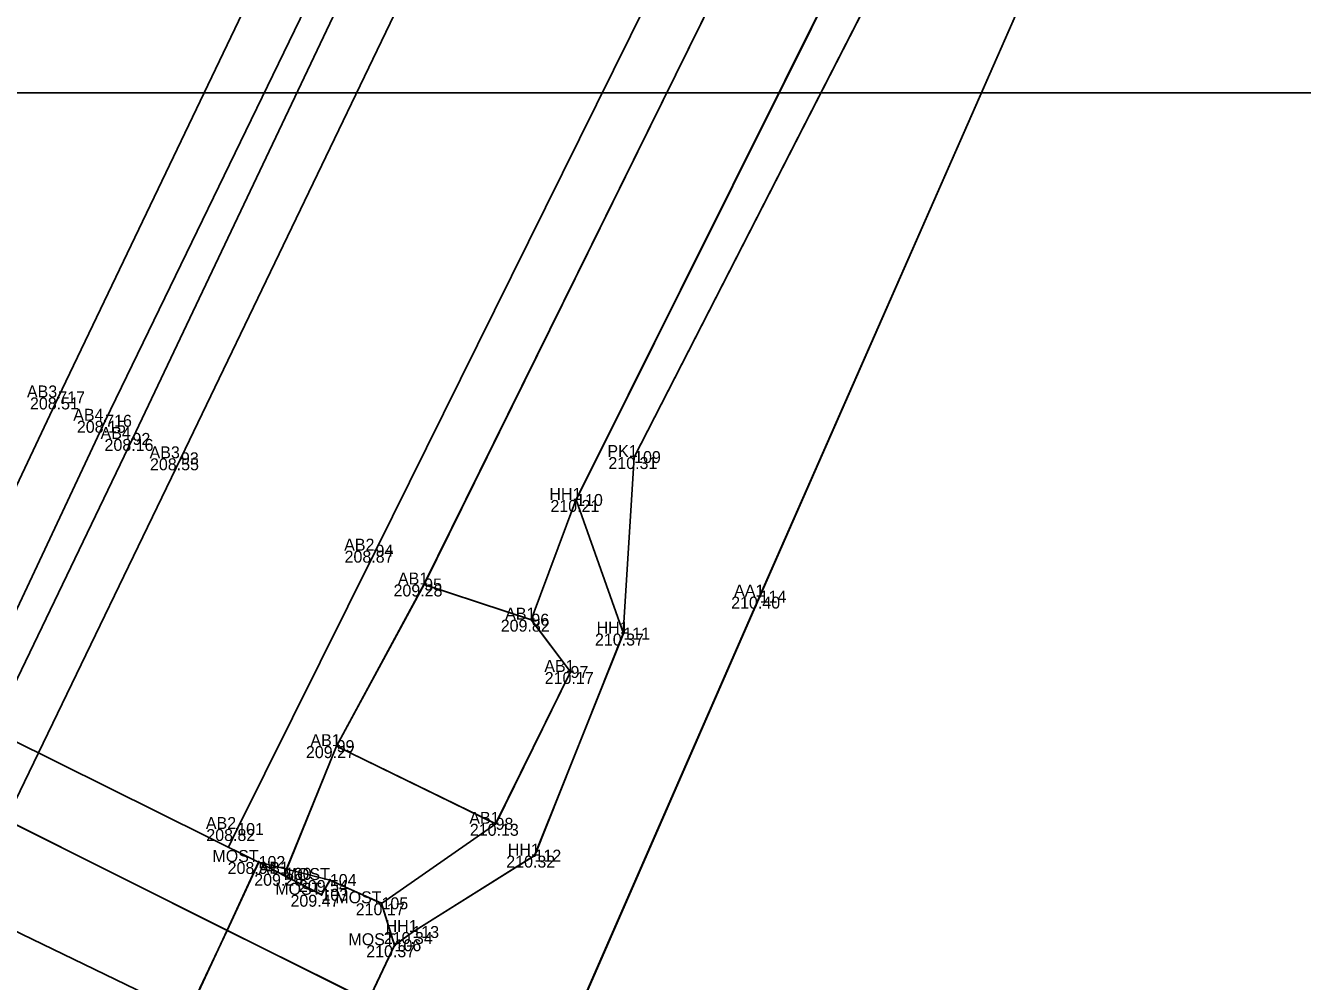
# Model space of a CAD drawing. Extents: x -263091 to -262565, y -1238731 to -1237092.
# Drawn here: x -262786.65 to -262765.31, y -1237679.73 to -1237663.76 of the extents above; entities that cross this region are included whole.
import ezdxf

# ---------------------------------------------------------------- set-up
doc = ezdxf.new("R2010")
doc.units = 0
for name, color, linetype in [('01_Hrana_betónu', 7, 'Continuous'), ('02_Oplotenie', 7, 'Continuous'), ('03_Asfalt', 7, 'Continuous'), ('04_Most', 7, 'Continuous'), ('05_Hrana_terénu', 7, 'Continuous'), ('07_Iné', 7, 'Continuous'), ('10', 7, 'Continuous'), ('Groma (21)', 7, 'Continuous'), ('Groma (22)', 7, 'Continuous'), ('Groma (23)', 7, 'Continuous'), ('Groma (24)', 7, 'Continuous'), ('U004_Betónové_panely', 7, 'Continuous'), ('U004_Ostatné_plochy', 7, 'Continuous'), ('U005_Betónové_panely', 7, 'Continuous'), ('U005_Betóny_prídavné', 7, 'Continuous'), ('U005_Ostatné_plochy', 7, 'Continuous'), ('U005_Zeleň_mimo', 7, 'Continuous'), ('U005_Zeleň_vnútro', 7, 'Continuous'), ('U005_Zeleň_zatrávňovač', 7, 'Continuous'), ('Vrstva 51', 7, 'Continuous')]:
    doc.layers.add(name, color=color, linetype=linetype)

msp = doc.modelspace()

# ---------------------------------------------------------------- linework, layer by layer
at = {"layer": '01_Hrana_betónu'}
for p, q in [((-262783.282, -1237678.876), (-262782.754, -1237677.736)), ((-262783.935, -1237680.285), (-262783.282, -1237678.876))]:
    msp.add_line(p, q, dxfattribs=at)
for points in [[(-262786.432, -1237675.911), (-262784.052, -1237670.991), (-262777.997, -1237658.39), (-262770.22, -1237641.884), (-262760.517, -1237621.621), (-262751.199, -1237602.266), (-262746.917, -1237592.345), (-262743.67, -1237583.59), (-262741.234, -1237574.416), (-262739.924, -1237566.213), (-262738.929, -1237556.596), (-262738.741, -1237547.665), (-262738.506, -1237524.618), (-262738.316, -1237501.393), (-262738.103, -1237478.98), (-262737.841, -1237459.175), (-262737.82, -1237425.07), (-262737.772, -1237401.714), (-262737.893, -1237377.738), (-262738.012, -1237356.488), (-262737.973, -1237332.295), (-262738.006, -1237318.022), (-262737.947, -1237310.645)], [(-262738.855, -1237311.192), (-262738.946, -1237318.051), (-262738.849, -1237332.413), (-262738.867, -1237356.312), (-262738.748, -1237377.69), (-262738.758, -1237401.69), (-262738.753, -1237425.185), (-262738.668, -1237459.096), (-262739.01, -1237478.875), (-262739.257, -1237501.361), (-262739.436, -1237524.506), (-262739.635, -1237547.624), (-262739.863, -1237556.5), (-262740.784, -1237566.075), (-262742.123, -1237574.161), (-262744.555, -1237583.315), (-262747.793, -1237592.067), (-262752.033, -1237601.877), (-262761.381, -1237621.164), (-262771.059, -1237641.465), (-262778.806, -1237657.918), (-262784.861, -1237670.667), (-262787.201, -1237675.529)], [(-262739.343, -1237311.485), (-262739.423, -1237318.909), (-262739.337, -1237332.42), (-262739.334, -1237355.849), (-262739.135, -1237377.701), (-262739.178, -1237401.786), (-262739.257, -1237424.031), (-262739.458, -1237458.924), (-262739.421, -1237479.296), (-262739.718, -1237500.116), (-262739.917, -1237524.824), (-262740.163, -1237546.913), (-262740.342, -1237556.649), (-262741.144, -1237564.78), (-262742.646, -1237573.838), (-262744.715, -1237582.455), (-262748.007, -1237591.229), (-262752.529, -1237601.669), (-262761.584, -1237620.386), (-262771.44, -1237641.076), (-262779.114, -1237657.574), (-262785.318, -1237670.364), (-262787.643, -1237675.31)], [(-262788.441, -1237674.914), (-262786.102, -1237669.974), (-262779.96, -1237657.146), (-262772.255, -1237640.671), (-262762.405, -1237620.082), (-262753.353, -1237601.237), (-262748.855, -1237590.92), (-262745.54, -1237582.117), (-262743.431, -1237573.688), (-262742.016, -1237564.7), (-262741.168, -1237556.501), (-262740.979, -1237546.892), (-262740.851, -1237524.752), (-262740.671, -1237500.08), (-262740.394, -1237479.483), (-262740.216, -1237458.955), (-262740.117, -1237423.647), (-262740.094, -1237401.75), (-262740.13, -1237377.708), (-262740.243, -1237355.929), (-262740.317, -1237332.345), (-262740.44, -1237318.894), (-262740.323, -1237312.076)], [(-262783.258, -1237677.486), (-262783.111, -1237677.185), (-262780.8, -1237672.534), (-262774.552, -1237659.911), (-262766.786, -1237643.656), (-262757.035, -1237623.248), (-262747.974, -1237603.808), (-262743.592, -1237593.531), (-262740.333, -1237584.524), (-262737.7, -1237574.963), (-262736.283, -1237566.732), (-262735.575, -1237556.629), (-262735.369, -1237547.722), (-262734.981, -1237524.159), (-262734.838, -1237501.704)], [(-262782.326, -1237677.959), (-262781.45, -1237675.8), (-262779.987, -1237673.099), (-262773.679, -1237660.319), (-262765.958, -1237644.106), (-262756.238, -1237623.625), (-262747.207, -1237604.197), (-262742.811, -1237593.79), (-262739.484, -1237584.835), (-262736.846, -1237575.127), (-262735.426, -1237566.88), (-262734.686, -1237556.753), (-262734.467, -1237547.755), (-262734.294, -1237524.216), (-262733.894, -1237501.859)], [(-262786.974, -1237677.031), (-262786.432, -1237675.911)]]:
    msp.add_lwpolyline(points, dxfattribs=at)
at = {"layer": '02_Oplotenie'}
msp.add_lwpolyline([(-262728.456, -1237307.793), (-262728.519, -1237318.579), (-262728.768, -1237332.338), (-262729.377, -1237356.238), (-262730.032, -1237378.843), (-262730.564, -1237401.661), (-262730.923, -1237425.563), (-262730.973, -1237458.163), (-262731.252, -1237478.578), (-262731.235, -1237502.529), (-262731.31, -1237524.311), (-262731.953, -1237547.895), (-262732.188, -1237556.779), (-262732.808, -1237567.174), (-262734.162, -1237576.139), (-262736.979, -1237586.017), (-262740.293, -1237594.798), (-262745.086, -1237605.537), (-262753.698, -1237624.773), (-262762.903, -1237643.627), (-262772.016, -1237662.266), (-262776.478, -1237670.97)], dxfattribs=at)
at = {"layer": '03_Asfalt'}
msp.add_lwpolyline([(-262724.746, -1237307.401), (-262727.828, -1237308.991), (-262728.093, -1237318.612), (-262728.491, -1237332.383), (-262729.117, -1237356.253), (-262729.803, -1237378.892), (-262730.272, -1237401.612), (-262730.633, -1237425.617), (-262730.625, -1237458.196), (-262731.018, -1237478.61), (-262730.917, -1237502.542), (-262731.001, -1237524.284), (-262731.468, -1237547.904), (-262731.892, -1237556.788), (-262732.535, -1237567.203), (-262733.679, -1237576.214), (-262736.504, -1237586.306), (-262740.104, -1237594.868), (-262744.783, -1237605.686), (-262753.189, -1237625.134), (-262761.527, -1237644.232), (-262769.984, -1237663.306), (-262774.379, -1237673.302), (-262777.928, -1237681.411)], dxfattribs=at)
at = {"layer": '04_Most'}
for points in [[(-262794.832, -1237673.105), (-262794.423, -1237672.239), (-262794.016, -1237671.765), (-262792.919, -1237672.236), (-262791.945, -1237673.175), (-262782.754, -1237677.736), (-262781.704, -1237678.283), (-262781.563, -1237678.037), (-262780.7, -1237678.426), (-262780.481, -1237679.127), (-262780.925, -1237680.054)], [(-262780.925, -1237680.054), (-262781.499, -1237681.254), (-262782.189, -1237681.436), (-262783, -1237681.174), (-262782.961, -1237680.851), (-262783.935, -1237680.285), (-262793.299, -1237675.758), (-262794.227, -1237675.288), (-262794.619, -1237675.515), (-262795.493, -1237674.504), (-262794.832, -1237673.105)]]:
    msp.add_lwpolyline(points, dxfattribs=at)
at = {"layer": '05_Hrana_terénu'}
msp.add_lwpolyline([(-262780.481, -1237679.127), (-262780.184, -1237678.906), (-262778.142, -1237677.63), (-262776.658, -1237673.919), (-262777.447, -1237671.687), (-262772.207, -1237661.172), (-262764.249, -1237644.683), (-262754.484, -1237624.262), (-262745.614, -1237605.143), (-262741.062, -1237594.471), (-262737.644, -1237585.61), (-262735.075, -1237575.555), (-262733.583, -1237567.143), (-262732.968, -1237556.742), (-262732.631, -1237547.918), (-262732.158, -1237524.14), (-262732.188, -1237502.434)], dxfattribs=at)
at = {"layer": '07_Iné'}
msp.add_lwpolyline([(-262781.45, -1237675.8), (-262778.794, -1237677.098), (-262777.541, -1237674.561), (-262778.195, -1237673.687), (-262779.987, -1237673.099)], dxfattribs=at)
at = {"layer": '10'}
msp.add_lwpolyline([(-262813.033, -1237664.011), (-262780.925, -1237680.054), (-262777.93, -1237681.41), (-262750.961, -1237695.025)], dxfattribs=at)
at = {"layer": 'Groma (21)'}
for centre in [(-262786.102, -1237669.974), (-262785.318, -1237670.364), (-262784.861, -1237670.667), (-262784.052, -1237670.991), (-262776.478, -1237670.97), (-262777.447, -1237671.687), (-262780.8, -1237672.534), (-262779.987, -1237673.099), (-262774.379, -1237673.302), (-262778.195, -1237673.687), (-262776.658, -1237673.919), (-262777.541, -1237674.561), (-262781.45, -1237675.8), (-262783.111, -1237677.185), (-262778.794, -1237677.098), (-262778.142, -1237677.63), (-262782.754, -1237677.736), (-262782.315, -1237677.933), (-262781.563, -1237678.037), (-262781.704, -1237678.283), (-262780.7, -1237678.426), (-262780.184, -1237678.906), (-262780.481, -1237679.127)]:
    msp.add_circle(centre, 0.01, dxfattribs=at)
at = {"layer": 'U004_Betónové_panely'}
msp.add_lwpolyline([(-262809.47, -1237744.21), (-262809.35, -1237719.32), (-262807.76, -1237709.13), (-262805.58, -1237701.26), (-262801.1, -1237689.83), (-262795.06, -1237676.27), (-262794.18, -1237676.61), (-262793.3, -1237675.76), (-262792.52, -1237674.26), (-262788.97, -1237676.03), (-262788.17, -1237676.43), (-262787.74, -1237676.65), (-262786.97, -1237677.03), (-262783.28, -1237678.88), (-262783.94, -1237680.28), (-262783.8, -1237680.36), (-262791.07, -1237697.73), (-262794.16, -1237706.2), (-262796.11, -1237713.49), (-262797.35, -1237722.8)], dxfattribs=at)
msp.add_lwpolyline([(-262809.47, -1237744.21), (-262809.35, -1237719.32), (-262807.76, -1237709.13), (-262805.58, -1237701.26), (-262801.1, -1237689.83), (-262795.06, -1237676.27), (-262794.18, -1237676.61), (-262793.3, -1237675.76), (-262792.52, -1237674.26), (-262788.97, -1237676.03), (-262788.17, -1237676.43), (-262787.74, -1237676.65), (-262786.97, -1237677.03), (-262783.28, -1237678.88), (-262783.94, -1237680.28), (-262783.8, -1237680.36), (-262791.07, -1237697.73), (-262794.16, -1237706.2), (-262796.11, -1237713.49), (-262797.35, -1237722.8)], dxfattribs=at)
at = {"layer": 'U004_Ostatné_plochy'}
msp.add_lwpolyline([(-262783.94, -1237680.28), (-262783.28, -1237678.88), (-262780.92, -1237680.05), (-262781.5, -1237681.25), (-262782.19, -1237681.44), (-262783, -1237681.17), (-262782.96, -1237680.85)], close=True, dxfattribs=at)
msp.add_lwpolyline([(-262782.19, -1237681.44), (-262783, -1237681.17), (-262782.96, -1237680.85), (-262783.94, -1237680.28), (-262783.28, -1237678.88), (-262780.92, -1237680.05), (-262781.5, -1237681.25), (-262782.19, -1237681.44)], dxfattribs=at)
at = {"layer": 'U005_Betónové_panely'}
for points in [[(-262783.28, -1237678.88), (-262786.97, -1237677.03), (-262787.74, -1237676.65), (-262788.17, -1237676.43), (-262788.97, -1237676.03), (-262792.52, -1237674.26), (-262791.95, -1237673.18), (-262792.03, -1237673.09), (-262792.68, -1237672.47), (-262784.42, -1237654.97), (-262776.68, -1237638.57), (-262766.09, -1237616.91), (-262757.49, -1237599.38), (-262752.94, -1237589.38), (-262749.71, -1237580.8), (-262747.5, -1237571.72), (-262746.49, -1237564.41), (-262745.67, -1237555.98), (-262745.34, -1237545.32), (-262745.22, -1237524.74), (-262745.02, -1237500.51)], [(-262733.89, -1237501.86), (-262734.29, -1237524.22), (-262734.47, -1237547.76), (-262734.69, -1237556.75), (-262735.43, -1237566.88), (-262736.85, -1237575.13), (-262739.48, -1237584.84), (-262742.81, -1237593.79), (-262747.21, -1237604.2), (-262756.24, -1237623.63), (-262765.96, -1237644.11), (-262773.68, -1237660.32), (-262779.99, -1237673.1), (-262781.45, -1237675.8), (-262782.33, -1237677.96), (-262782.75, -1237677.74), (-262783.28, -1237678.88)], [(-262747.21, -1237604.2), (-262756.24, -1237623.63), (-262765.96, -1237644.11), (-262773.68, -1237660.32), (-262779.99, -1237673.1), (-262781.45, -1237675.8), (-262782.33, -1237677.96), (-262782.75, -1237677.74), (-262783.28, -1237678.88), (-262786.97, -1237677.03), (-262787.74, -1237676.65), (-262788.17, -1237676.43), (-262788.97, -1237676.03), (-262792.52, -1237674.26), (-262791.95, -1237673.18), (-262792.03, -1237673.09), (-262792.68, -1237672.47), (-262784.42, -1237654.97), (-262776.68, -1237638.57), (-262766.09, -1237616.91)]]:
    msp.add_lwpolyline(points, dxfattribs=at)
at = {"layer": 'U005_Betóny_prídavné'}
msp.add_lwpolyline([(-262778.2, -1237673.69), (-262777.54, -1237674.56), (-262778.79, -1237677.1), (-262781.45, -1237675.8), (-262779.99, -1237673.1)], close=True, dxfattribs=at)
msp.add_lwpolyline([(-262778.79, -1237677.1), (-262781.45, -1237675.8), (-262779.99, -1237673.1), (-262778.2, -1237673.69), (-262777.54, -1237674.56), (-262778.79, -1237677.1)], dxfattribs=at)
at = {"layer": 'U005_Ostatné_plochy'}
msp.add_lwpolyline([(-262783.28, -1237678.88), (-262782.75, -1237677.74), (-262781.56, -1237678.04), (-262780.7, -1237678.43), (-262780.48, -1237679.13), (-262780.92, -1237680.05)], close=True, dxfattribs=at)
msp.add_lwpolyline([(-262780.92, -1237680.05), (-262783.28, -1237678.88), (-262782.75, -1237677.74), (-262781.56, -1237678.04), (-262780.7, -1237678.43), (-262780.48, -1237679.13), (-262780.92, -1237680.05)], dxfattribs=at)
at = {"layer": 'U005_Zeleň_mimo'}
msp.add_lwpolyline([(-262744.78, -1237605.69), (-262753.19, -1237625.13), (-262761.53, -1237644.23), (-262769.98, -1237663.31), (-262774.38, -1237673.3), (-262777.93, -1237681.41), (-262780.92, -1237680.05), (-262780.48, -1237679.13), (-262780.18, -1237678.91), (-262778.14, -1237677.63), (-262776.66, -1237673.92), (-262776.48, -1237670.97), (-262772.02, -1237662.27), (-262762.9, -1237643.63), (-262753.7, -1237624.77), (-262745.09, -1237605.54)], dxfattribs=at)
at = {"layer": 'U005_Zeleň_vnútro'}
for points in [[(-262780.48, -1237679.13), (-262780.7, -1237678.43), (-262778.79, -1237677.1), (-262777.54, -1237674.56), (-262778.2, -1237673.69), (-262777.45, -1237671.69), (-262772.21, -1237661.17), (-262764.25, -1237644.68), (-262754.48, -1237624.26), (-262745.61, -1237605.14), (-262741.06, -1237594.47), (-262737.64, -1237585.61), (-262735.08, -1237575.56), (-262733.58, -1237567.14), (-262732.97, -1237556.74), (-262732.63, -1237547.92), (-262732.16, -1237524.14), (-262732.19, -1237502.43)], [(-262731.24, -1237502.53), (-262731.31, -1237524.31), (-262731.95, -1237547.9), (-262732.19, -1237556.78), (-262732.81, -1237567.17), (-262734.16, -1237576.14), (-262736.98, -1237586.02), (-262740.29, -1237594.8), (-262745.09, -1237605.54), (-262753.7, -1237624.77), (-262762.9, -1237643.63), (-262772.02, -1237662.27), (-262776.48, -1237670.97), (-262776.66, -1237673.92), (-262778.14, -1237677.63), (-262780.18, -1237678.91), (-262780.48, -1237679.13)], [(-262745.09, -1237605.54), (-262753.7, -1237624.77), (-262762.9, -1237643.63), (-262772.02, -1237662.27), (-262776.48, -1237670.97), (-262776.66, -1237673.92), (-262778.14, -1237677.63), (-262780.18, -1237678.91), (-262780.48, -1237679.13), (-262780.7, -1237678.43), (-262778.79, -1237677.1), (-262777.54, -1237674.56), (-262778.2, -1237673.69), (-262777.45, -1237671.69), (-262772.21, -1237661.17), (-262764.25, -1237644.68), (-262754.48, -1237624.26), (-262745.61, -1237605.14)]]:
    msp.add_lwpolyline(points, dxfattribs=at)
at = {"layer": 'U005_Zeleň_zatrávňovač'}
for points in [[(-262778.2, -1237673.69), (-262779.99, -1237673.1), (-262773.68, -1237660.32), (-262765.96, -1237644.11), (-262756.24, -1237623.63), (-262747.21, -1237604.2), (-262742.81, -1237593.79), (-262739.48, -1237584.84), (-262736.85, -1237575.13), (-262735.43, -1237566.88), (-262734.69, -1237556.75), (-262734.47, -1237547.76), (-262734.29, -1237524.22), (-262733.89, -1237501.86)], [(-262732.19, -1237502.43), (-262732.16, -1237524.14), (-262732.63, -1237547.92), (-262732.97, -1237556.74), (-262733.58, -1237567.14), (-262735.08, -1237575.56), (-262737.64, -1237585.61), (-262741.06, -1237594.47), (-262745.61, -1237605.14), (-262754.48, -1237624.26), (-262764.25, -1237644.68), (-262772.21, -1237661.17), (-262777.45, -1237671.69), (-262778.2, -1237673.69)], [(-262745.61, -1237605.14), (-262754.48, -1237624.26), (-262764.25, -1237644.68), (-262772.21, -1237661.17), (-262777.45, -1237671.69), (-262778.2, -1237673.69), (-262779.99, -1237673.1), (-262773.68, -1237660.32), (-262765.96, -1237644.11), (-262756.24, -1237623.63), (-262747.21, -1237604.2)], [(-262780.7, -1237678.43), (-262781.56, -1237678.04), (-262781.7, -1237678.28), (-262782.33, -1237677.96), (-262781.45, -1237675.8), (-262778.79, -1237677.1), (-262780.7, -1237678.43)]]:
    msp.add_lwpolyline(points, dxfattribs=at)
msp.add_lwpolyline([(-262781.56, -1237678.04), (-262781.7, -1237678.28), (-262782.33, -1237677.96), (-262781.45, -1237675.8), (-262778.79, -1237677.1), (-262780.7, -1237678.43)], close=True, dxfattribs=at)
at = {"layer": 'Vrstva 51'}
msp.add_lwpolyline([(-262609.436, -1238258.884), (-263029.436, -1238258.884), (-263029.436, -1237664.884), (-262609.436, -1237664.884)], close=True, dxfattribs=at)

# ---------------------------------------------------------------- texts
at = {"layer": 'Groma (22)'}
for s, p in [('717', (-262786.102, -1237670.074)), ('716', (-262785.318, -1237670.464)), ('92', (-262784.861, -1237670.767)), ('109', (-262776.478, -1237671.07)), ('93', (-262784.052, -1237671.091)), ('110', (-262777.447, -1237671.787)), ('94', (-262780.8, -1237672.634)), ('95', (-262779.987, -1237673.199)), ('114', (-262774.379, -1237673.402)), ('96', (-262778.195, -1237673.787)), ('111', (-262776.658, -1237674.019)), ('97', (-262777.541, -1237674.661)), ('99', (-262781.45, -1237675.9)), ('98', (-262778.794, -1237677.198)), ('101', (-262783.111, -1237677.285)), ('102', (-262782.754, -1237677.836)), ('112', (-262778.142, -1237677.73)), ('100', (-262782.315, -1237678.033)), ('104', (-262781.563, -1237678.137)), ('103', (-262781.704, -1237678.383)), ('105', (-262780.7, -1237678.526)), ('113', (-262780.184, -1237679.006)), ('106', (-262780.481, -1237679.227))]:
    msp.add_text(s, height=0.2, dxfattribs=at).set_placement(p)
at = {"layer": 'Groma (23)'}
for s, p in [('208.51', (-262786.575, -1237670.174)), ('208.15', (-262785.791, -1237670.564)), ('208.16', (-262785.329, -1237670.867)), ('208.55', (-262784.569, -1237671.191)), ('210.31', (-262776.908, -1237671.17)), ('210.21', (-262777.877, -1237671.887)), ('208.87', (-262781.317, -1237672.734)), ('209.28', (-262780.499, -1237673.299)), ('210.40', (-262774.856, -1237673.502)), ('209.82', (-262778.707, -1237673.887)), ('210.37', (-262777.132, -1237674.119)), ('210.17', (-262777.972, -1237674.761)), ('209.27', (-262781.963, -1237676)), ('208.82', (-262783.628, -1237677.385)), ('210.13', (-262779.224, -1237677.298)), ('210.32', (-262778.615, -1237677.83)), ('208.94', (-262783.271, -1237677.936)), ('209.28', (-262782.827, -1237678.133)), ('209.54', (-262782.08, -1237678.237)), ('209.47', (-262782.221, -1237678.483)), ('210.17', (-262781.131, -1237678.626)), ('210.34', (-262780.662, -1237679.106)), ('210.37', (-262780.955, -1237679.327))]:
    msp.add_text(s, height=0.2, dxfattribs=at).set_placement(p)
at = {"layer": 'Groma (24)'}
for s, p in [('AB3', (-262786.626, -1237669.974)), ('AB4', (-262785.852, -1237670.364)), ('AB4', (-262785.395, -1237670.667)), ('AB3', (-262784.576, -1237670.991)), ('PK1', (-262776.925, -1237670.97)), ('HH1', (-262777.894, -1237671.687)), ('AB2', (-262781.324, -1237672.534)), ('AB1', (-262780.425, -1237673.099)), ('AA1', (-262774.807, -1237673.302)), ('AB1', (-262778.633, -1237673.687)), ('HH1', (-262777.105, -1237673.919)), ('AB1', (-262777.979, -1237674.561)), ('AB1', (-262781.888, -1237675.8)), ('AB2', (-262783.635, -1237677.185)), ('AB1', (-262779.232, -1237677.098)), ('HH1', (-262778.589, -1237677.63)), ('MOST', (-262783.526, -1237677.736)), ('AB1', (-262782.753, -1237677.933)), ('MOST', (-262782.335, -1237678.037)), ('MOST', (-262782.476, -1237678.283)), ('MOST', (-262781.472, -1237678.426)), ('HH1', (-262780.631, -1237678.906)), ('MOST', (-262781.253, -1237679.127))]:
    msp.add_text(s, height=0.2, dxfattribs=at).set_placement(p)

doc.saveas('drawing.dxf')
